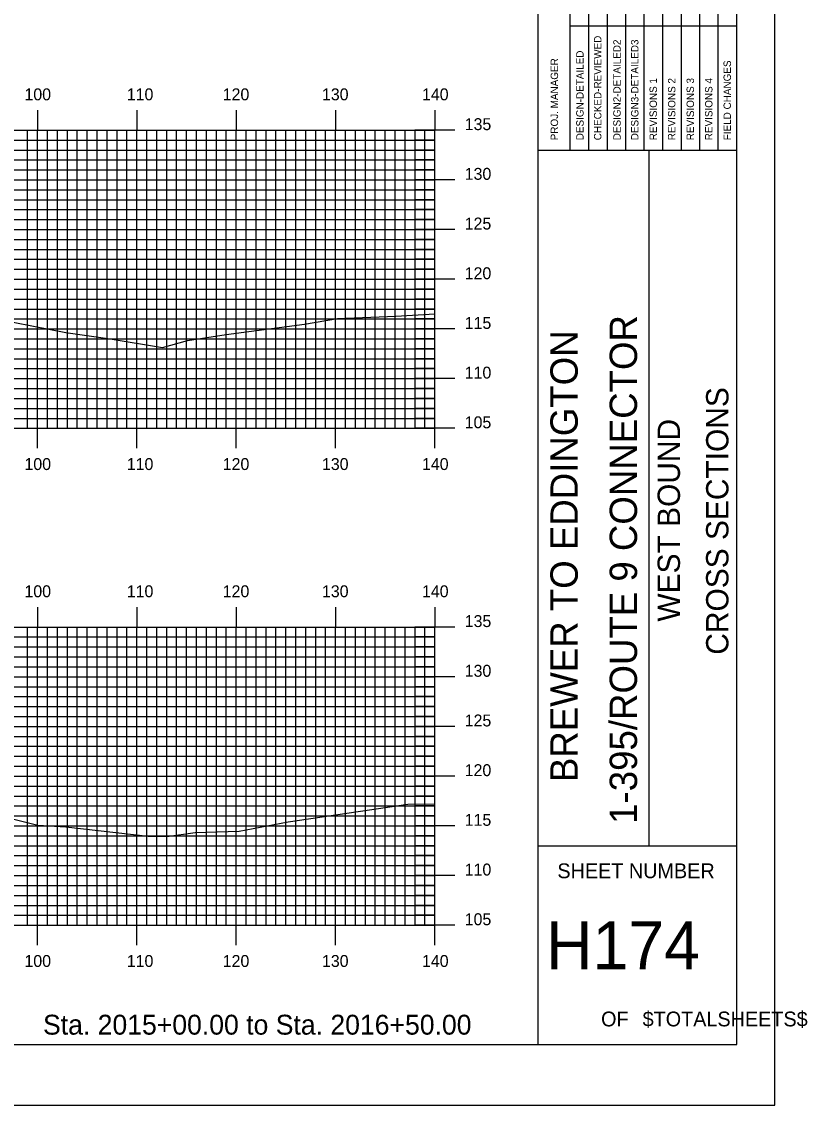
# Model space of a CAD drawing. Extents: x 854681 to 855024, y 366605 to 366825.
# Drawn here: x 854945 to 855024.1, y 366604.9 to 366714 of the extents above; entities that cross this region are included whole.
import ezdxf

# ---------------------------------------------------------------- set-up
doc = ezdxf.new("R2010")
doc.units = 0
for name, color, linetype in [('BORDER', 7, 'Continuous'), ('H_V ANNOTATION', 7, 'Continuous'), ('MAJOR', 7, 'Continuous'), ('MINOR', 7, 'Continuous'), ('PLOT BOUNDARY', 7, 'Continuous'), ('S_Roadway_Centerline', 7, 'Continuous')]:
    doc.layers.add(name, color=color, linetype=linetype)

msp = doc.modelspace()

# ---------------------------------------------------------------- linework, layer by layer
at = {"layer": 'BORDER'}
for p, q in [((854996.96, 366611.06), (854996.96, 366821.06)), ((854996.96, 366701.06), (855016.96, 366701.06)), ((855008.14, 366631.06), (855008.14, 366701.06)), ((854996.96, 366631.06), (855016.96, 366631.06))]:
    msp.add_line(p, q, dxfattribs=at)
msp.add_lwpolyline([(854696.96, 366611.06), (855016.96, 366611.06), (855016.96, 366821.06), (854696.96, 366821.06)], close=True, dxfattribs=at)
for points in [[(855002.05, 366701.07), (855002.05, 366736.06)], [(855003.91, 366736.06), (855003.91, 366701.07)], [(855005.78, 366701.07), (855005.78, 366736.06)], [(855007.64, 366701.07), (855007.64, 366736.06)], [(855009.5, 366701.07), (855009.5, 366736.06)], [(855011.37, 366701.07), (855011.37, 366736.06)], [(855013.23, 366701.07), (855013.23, 366736.06)], [(855015.09, 366701.07), (855015.09, 366736.06)], [(855000.19, 366701.07), (855000.19, 366734.65)], [(855000.19, 366713.56), (855016.96, 366713.56)]]:
    msp.add_lwpolyline(points, dxfattribs=at)
at = {"layer": 'MAJOR'}
for p, q in [((854946.56, 366705.06), (854946.56, 366703.06)), ((854956.56, 366705.06), (854956.56, 366703.06)), ((854966.56, 366705.06), (854966.56, 366703.06)), ((854976.56, 366705.06), (854976.56, 366703.06)), ((854986.56, 366705.06), (854986.56, 366703.06)), ((854706.56, 366703.06), (854986.56, 366703.06)), ((854706.56, 366703.06), (854986.56, 366703.06)), ((854946.56, 366673.06), (854946.56, 366703.06)), ((854956.56, 366673.06), (854956.56, 366703.06)), ((854966.56, 366673.06), (854966.56, 366703.06)), ((854976.56, 366673.06), (854976.56, 366703.06)), ((854988.56, 366703.06), (854984.55, 366703.06)), ((854986.56, 366673.06), (854986.56, 366703.06)), ((854986.56, 366673.06), (854986.56, 366703.06)), ((854706.56, 366698.06), (854986.56, 366698.06)), ((854988.56, 366698.06), (854984.55, 366698.06)), ((854706.56, 366693.06), (854986.56, 366693.06)), ((854988.56, 366693.06), (854984.55, 366693.06)), ((854706.56, 366688.06), (854986.56, 366688.06)), ((854988.56, 366688.06), (854984.55, 366688.06)), ((854706.56, 366683.06), (854986.56, 366683.06)), ((854988.56, 366683.06), (854984.55, 366683.06)), ((854706.56, 366678.06), (854986.56, 366678.06)), ((854988.56, 366678.06), (854984.55, 366678.06)), ((854706.56, 366673.06), (854986.56, 366673.06)), ((854706.56, 366673.06), (854986.56, 366673.06)), ((854946.56, 366671.05), (854946.56, 366673.06)), ((854956.56, 366671.05), (854956.56, 366673.06)), ((854966.56, 366671.05), (854966.56, 366673.06)), ((854976.56, 366671.05), (854976.56, 366673.06)), ((854988.56, 366673.06), (854984.55, 366673.06)), ((854986.56, 366671.05), (854986.56, 366673.06)), ((854946.56, 366655.06), (854946.56, 366653.06)), ((854956.56, 366655.06), (854956.56, 366653.06)), ((854966.56, 366655.06), (854966.56, 366653.06)), ((854976.56, 366655.06), (854976.56, 366653.06)), ((854986.56, 366655.06), (854986.56, 366653.06)), ((854706.56, 366653.06), (854986.56, 366653.06)), ((854706.56, 366653.06), (854986.56, 366653.06)), ((854946.56, 366623.06), (854946.56, 366653.06)), ((854956.56, 366623.06), (854956.56, 366653.06)), ((854966.56, 366623.06), (854966.56, 366653.06)), ((854976.56, 366623.06), (854976.56, 366653.06)), ((854988.56, 366653.06), (854984.55, 366653.06)), ((854986.56, 366623.06), (854986.56, 366653.06)), ((854986.56, 366623.06), (854986.56, 366653.06)), ((854706.56, 366648.06), (854986.56, 366648.06)), ((854988.56, 366648.06), (854984.55, 366648.06)), ((854706.56, 366643.06), (854986.56, 366643.06)), ((854988.56, 366643.06), (854984.55, 366643.06)), ((854706.56, 366638.06), (854986.56, 366638.06)), ((854988.56, 366638.06), (854984.55, 366638.06)), ((854706.56, 366633.06), (854986.56, 366633.06)), ((854988.56, 366633.06), (854984.55, 366633.06)), ((854706.56, 366628.06), (854986.56, 366628.06)), ((854988.56, 366628.06), (854984.55, 366628.06)), ((854706.56, 366623.06), (854986.56, 366623.06)), ((854706.56, 366623.06), (854986.56, 366623.06)), ((854946.56, 366621.05), (854946.56, 366623.06)), ((854956.56, 366621.05), (854956.56, 366623.06)), ((854966.56, 366621.05), (854966.56, 366623.06)), ((854976.56, 366621.05), (854976.56, 366623.06)), ((854988.56, 366623.06), (854984.55, 366623.06)), ((854986.56, 366621.05), (854986.56, 366623.06))]:
    msp.add_line(p, q, dxfattribs=at)
at = {"layer": 'MINOR'}
for p, q in [((854945.56, 366673.06), (854945.56, 366703.06)), ((854947.56, 366673.06), (854947.56, 366703.06)), ((854948.56, 366673.06), (854948.56, 366703.06)), ((854949.56, 366673.06), (854949.56, 366703.06)), ((854950.56, 366673.06), (854950.56, 366703.06)), ((854951.56, 366673.06), (854951.56, 366703.06)), ((854952.56, 366673.06), (854952.56, 366703.06)), ((854953.56, 366673.06), (854953.56, 366703.06)), ((854954.56, 366673.06), (854954.56, 366703.06)), ((854955.56, 366673.06), (854955.56, 366703.06)), ((854957.56, 366673.06), (854957.56, 366703.06)), ((854958.56, 366673.06), (854958.56, 366703.06)), ((854959.56, 366673.06), (854959.56, 366703.06)), ((854960.56, 366673.06), (854960.56, 366703.06)), ((854961.56, 366673.06), (854961.56, 366703.06)), ((854962.56, 366673.06), (854962.56, 366703.06)), ((854963.56, 366673.06), (854963.56, 366703.06)), ((854964.56, 366673.06), (854964.56, 366703.06)), ((854965.56, 366673.06), (854965.56, 366703.06)), ((854967.56, 366673.06), (854967.56, 366703.06)), ((854968.56, 366673.06), (854968.56, 366703.06)), ((854969.56, 366673.06), (854969.56, 366703.06)), ((854970.56, 366673.06), (854970.56, 366703.06)), ((854971.56, 366673.06), (854971.56, 366703.06)), ((854972.56, 366673.06), (854972.56, 366703.06)), ((854973.56, 366673.06), (854973.56, 366703.06)), ((854974.56, 366673.06), (854974.56, 366703.06)), ((854975.56, 366673.06), (854975.56, 366703.06)), ((854977.56, 366673.06), (854977.56, 366703.06)), ((854978.56, 366673.06), (854978.56, 366703.06)), ((854979.56, 366673.06), (854979.56, 366703.06)), ((854980.56, 366673.06), (854980.56, 366703.06)), ((854981.56, 366673.06), (854981.56, 366703.06)), ((854982.56, 366673.06), (854982.56, 366703.06)), ((854983.56, 366673.06), (854983.56, 366703.06)), ((854984.56, 366673.06), (854984.56, 366703.06)), ((854985.56, 366673.06), (854985.56, 366703.06)), ((854706.56, 366702.06), (854986.56, 366702.06)), ((854986.56, 366702.06), (854984.55, 366702.06)), ((854706.56, 366701.06), (854986.56, 366701.06)), ((854986.56, 366701.06), (854984.55, 366701.06)), ((854706.56, 366700.06), (854986.56, 366700.06)), ((854986.56, 366700.06), (854984.55, 366700.06)), ((854706.56, 366699.06), (854986.56, 366699.06)), ((854986.56, 366699.06), (854984.55, 366699.06)), ((854706.56, 366697.06), (854986.56, 366697.06)), ((854986.56, 366697.06), (854984.55, 366697.06)), ((854706.56, 366696.06), (854986.56, 366696.06)), ((854986.56, 366696.06), (854984.55, 366696.06)), ((854706.56, 366695.06), (854986.56, 366695.06)), ((854986.56, 366695.06), (854984.55, 366695.06)), ((854706.56, 366694.06), (854986.56, 366694.06)), ((854986.56, 366694.06), (854984.55, 366694.06)), ((854706.56, 366692.06), (854986.56, 366692.06)), ((854986.56, 366692.06), (854984.55, 366692.06)), ((854706.56, 366691.06), (854986.56, 366691.06)), ((854986.56, 366691.06), (854984.55, 366691.06)), ((854706.56, 366690.06), (854986.56, 366690.06)), ((854986.56, 366690.06), (854984.55, 366690.06)), ((854706.56, 366689.06), (854986.56, 366689.06)), ((854986.56, 366689.06), (854984.55, 366689.06)), ((854706.56, 366687.06), (854986.56, 366687.06)), ((854706.56, 366686.06), (854986.56, 366686.06)), ((854986.56, 366687.06), (854984.55, 366687.06)), ((854986.56, 366686.06), (854984.55, 366686.06)), ((854706.56, 366685.06), (854986.56, 366685.06)), ((854986.56, 366685.06), (854984.55, 366685.06)), ((854706.56, 366684.06), (854986.56, 366684.06)), ((854986.56, 366684.06), (854984.55, 366684.06)), ((854706.56, 366682.06), (854986.56, 366682.06)), ((854986.56, 366682.06), (854984.55, 366682.06)), ((854706.56, 366681.06), (854986.56, 366681.06)), ((854986.56, 366681.06), (854984.55, 366681.06)), ((854706.56, 366680.06), (854986.56, 366680.06)), ((854986.56, 366680.06), (854984.55, 366680.06)), ((854706.56, 366679.06), (854986.56, 366679.06)), ((854986.56, 366679.06), (854984.55, 366679.06)), ((854706.56, 366677.06), (854986.56, 366677.06)), ((854986.56, 366677.06), (854984.55, 366677.06)), ((854706.56, 366676.06), (854986.56, 366676.06)), ((854986.56, 366676.06), (854984.55, 366676.06)), ((854706.56, 366675.06), (854986.56, 366675.06)), ((854706.56, 366674.06), (854986.56, 366674.06)), ((854986.56, 366675.06), (854984.55, 366675.06)), ((854986.56, 366674.06), (854984.55, 366674.06)), ((854945.56, 366623.06), (854945.56, 366653.06)), ((854947.56, 366623.06), (854947.56, 366653.06)), ((854948.56, 366623.06), (854948.56, 366653.06)), ((854949.56, 366623.06), (854949.56, 366653.06)), ((854950.56, 366623.06), (854950.56, 366653.06)), ((854951.56, 366623.06), (854951.56, 366653.06)), ((854952.56, 366623.06), (854952.56, 366653.06)), ((854953.56, 366623.06), (854953.56, 366653.06)), ((854954.56, 366623.06), (854954.56, 366653.06)), ((854955.56, 366623.06), (854955.56, 366653.06)), ((854957.56, 366623.06), (854957.56, 366653.06)), ((854958.56, 366623.06), (854958.56, 366653.06)), ((854959.56, 366623.06), (854959.56, 366653.06)), ((854960.56, 366623.06), (854960.56, 366653.06)), ((854961.56, 366623.06), (854961.56, 366653.06)), ((854962.56, 366623.06), (854962.56, 366653.06)), ((854963.56, 366623.06), (854963.56, 366653.06)), ((854964.56, 366623.06), (854964.56, 366653.06)), ((854965.56, 366623.06), (854965.56, 366653.06)), ((854967.56, 366623.06), (854967.56, 366653.06)), ((854968.56, 366623.06), (854968.56, 366653.06)), ((854969.56, 366623.06), (854969.56, 366653.06)), ((854970.56, 366623.06), (854970.56, 366653.06)), ((854971.56, 366623.06), (854971.56, 366653.06)), ((854972.56, 366623.06), (854972.56, 366653.06)), ((854973.56, 366623.06), (854973.56, 366653.06)), ((854974.56, 366623.06), (854974.56, 366653.06)), ((854975.56, 366623.06), (854975.56, 366653.06)), ((854977.56, 366623.06), (854977.56, 366653.06)), ((854978.56, 366623.06), (854978.56, 366653.06)), ((854979.56, 366623.06), (854979.56, 366653.06)), ((854980.56, 366623.06), (854980.56, 366653.06)), ((854981.56, 366623.06), (854981.56, 366653.06)), ((854982.56, 366623.06), (854982.56, 366653.06)), ((854983.56, 366623.06), (854983.56, 366653.06)), ((854984.56, 366623.06), (854984.56, 366653.06)), ((854985.56, 366623.06), (854985.56, 366653.06)), ((854706.56, 366652.06), (854986.56, 366652.06)), ((854986.56, 366652.06), (854984.55, 366652.06)), ((854706.56, 366651.06), (854986.56, 366651.06)), ((854706.56, 366650.06), (854986.56, 366650.06)), ((854986.56, 366651.06), (854984.55, 366651.06)), ((854986.56, 366650.06), (854984.55, 366650.06)), ((854706.56, 366649.06), (854986.56, 366649.06)), ((854986.56, 366649.06), (854984.55, 366649.06)), ((854706.56, 366647.06), (854986.56, 366647.06)), ((854986.56, 366647.06), (854984.55, 366647.06)), ((854706.56, 366646.06), (854986.56, 366646.06)), ((854986.56, 366646.06), (854984.55, 366646.06)), ((854706.56, 366645.06), (854986.56, 366645.06)), ((854986.56, 366645.06), (854984.55, 366645.06)), ((854706.56, 366644.06), (854986.56, 366644.06)), ((854986.56, 366644.06), (854984.55, 366644.06)), ((854706.56, 366642.06), (854986.56, 366642.06)), ((854986.56, 366642.06), (854984.55, 366642.06)), ((854706.56, 366641.06), (854986.56, 366641.06)), ((854986.56, 366641.06), (854984.55, 366641.06)), ((854706.56, 366640.06), (854986.56, 366640.06)), ((854986.56, 366640.06), (854984.55, 366640.06)), ((854706.56, 366639.06), (854986.56, 366639.06)), ((854986.56, 366639.06), (854984.55, 366639.06)), ((854706.56, 366637.06), (854986.56, 366637.06)), ((854986.56, 366637.06), (854984.55, 366637.06)), ((854706.56, 366636.06), (854986.56, 366636.06)), ((854986.56, 366636.06), (854984.55, 366636.06)), ((854706.56, 366635.06), (854986.56, 366635.06)), ((854986.56, 366635.06), (854984.55, 366635.06)), ((854706.56, 366634.06), (854986.56, 366634.06)), ((854986.56, 366634.06), (854984.55, 366634.06)), ((854706.56, 366632.06), (854986.56, 366632.06)), ((854986.56, 366632.06), (854984.55, 366632.06)), ((854706.56, 366631.06), (854986.56, 366631.06)), ((854986.56, 366631.06), (854984.55, 366631.06)), ((854706.56, 366630.06), (854986.56, 366630.06)), ((854986.56, 366630.06), (854984.55, 366630.06)), ((854706.56, 366629.06), (854986.56, 366629.06)), ((854986.56, 366629.06), (854984.55, 366629.06)), ((854706.56, 366627.06), (854986.56, 366627.06)), ((854706.56, 366626.06), (854986.56, 366626.06)), ((854986.56, 366627.06), (854984.55, 366627.06)), ((854986.56, 366626.06), (854984.55, 366626.06)), ((854706.56, 366625.06), (854986.56, 366625.06)), ((854986.56, 366625.06), (854984.55, 366625.06)), ((854706.56, 366624.06), (854986.56, 366624.06)), ((854986.56, 366624.06), (854984.55, 366624.06))]:
    msp.add_line(p, q, dxfattribs=at)
at = {"layer": 'PLOT BOUNDARY'}
msp.add_lwpolyline([(854680.77, 366604.94), (855020.77, 366604.94), (855020.77, 366824.94), (854680.77, 366824.94)], close=True, dxfattribs=at)
at = {"layer": 'S_Roadway_Centerline'}
for points in [[(854937.38, 366685.04), (854949.42, 366682.71), (854953.87, 366682.06), (854959.14, 366681.18), (854961.65, 366681.88), (854965.53, 366682.49), (854973.42, 366683.55), (854976.77, 366684.1), (854982.61, 366684.35), (854986.56, 366684.56)], [(854940.01, 366634.77), (854946.6, 366633.11), (854949.41, 366632.96), (854957.68, 366632.03), (854959.57, 366632), (854962.42, 366632.39), (854966.86, 366632.52), (854971.79, 366633.46), (854983.84, 366635.23), (854986.56, 366635.27)]]:
    msp.add_lwpolyline(points, dxfattribs=at)

# ---------------------------------------------------------------- texts
at = {"layer": 'BORDER'}
for s, height, p in [('CHECKED-REVIEWED', 0.7455, (855003.32, 366702.04)), ('DESIGN2-DETAILED2', 0.7455, (855005.26, 366702.04)), ('DESIGN3-DETAILED3', 0.7455, (855007.05, 366702.04)), ('PROJ. MANAGER', 0.7455, (854998.96, 366702.04)), ('DESIGN-DETAILED', 0.7455, (855001.53, 366702.04)), ('FIELD CHANGES', 0.7455, (855016.36, 366702.04)), ('REVISIONS 1', 0.7455, (855008.91, 366702.04)), ('REVISIONS 2', 0.7455, (855010.77, 366702.04)), ('REVISIONS 3', 0.7455, (855012.64, 366702.04)), ('REVISIONS 4', 0.7455, (855014.5, 366702.04)), ('1-395/ROUTE 9 CONNECTOR', 2.7557, (855006.91, 366633.26)), ('BREWER TO EDDINGTON', 2.7557, (855000.94, 366637.46)), ('CROSS SECTIONS', 2.25, (855016.11, 366650.28)), ('WEST BOUND', 2.25, (855011.23, 366653.61))]:
    msp.add_text(s, height=height, rotation=90, dxfattribs=at).set_placement(p)
for s, height, p in [('SHEET NUMBER', 1.4905, (854998.89, 366627.79)), ('H174', 4.839, (854997.76, 366618.62)), ('OF', 1.491, (855003.29, 366612.88)), ('$TOTALSHEETS$', 1.4905, (855007.47, 366612.88))]:
    msp.add_text(s, height=height, dxfattribs=at).set_placement(p)
at = {"layer": 'H_V ANNOTATION'}
for s, height, p in [('100', 1.2, (854945.24, 366706.06)), ('110', 1.2, (854955.54, 366706.06)), ('120', 1.2, (854965.2, 366706.06)), ('130', 1.2, (854975.19, 366706.06)), ('140', 1.2, (854985.26, 366706.06)), ('135', 1.2, (854989.56, 366703.06)), ('130', 1.2, (854989.56, 366698.06)), ('125', 1.2, (854989.56, 366693.06)), ('120', 1.2, (854989.56, 366688.06)), ('115', 1.2, (854989.56, 366683.06)), ('110', 1.2, (854989.56, 366678.06)), ('105', 1.2, (854989.56, 366673.06)), ('100', 1.2, (854945.24, 366668.86)), ('110', 1.2, (854955.54, 366668.86)), ('120', 1.2, (854965.2, 366668.86)), ('130', 1.2, (854975.19, 366668.86)), ('140', 1.2, (854985.26, 366668.86)), ('100', 1.2, (854945.24, 366656.06)), ('110', 1.2, (854955.54, 366656.06)), ('120', 1.2, (854965.2, 366656.06)), ('130', 1.2, (854975.19, 366656.06)), ('140', 1.2, (854985.26, 366656.06)), ('135', 1.2, (854989.56, 366653.06)), ('130', 1.2, (854989.56, 366648.06)), ('125', 1.2, (854989.56, 366643.06)), ('120', 1.2, (854989.56, 366638.06)), ('115', 1.2, (854989.56, 366633.06)), ('110', 1.2, (854989.56, 366628.06)), ('105', 1.2, (854989.56, 366623.06)), ('100', 1.2, (854945.24, 366618.86)), ('110', 1.2, (854955.54, 366618.86)), ('120', 1.2, (854965.2, 366618.86)), ('130', 1.2, (854975.19, 366618.86)), ('140', 1.2, (854985.26, 366618.86)), ('Sta. 2015+00.00 to Sta. 2016+50.00', 2.0004, (854947.11, 366612.05))]:
    msp.add_text(s, height=height, dxfattribs=at).set_placement(p)

doc.saveas('drawing.dxf')
